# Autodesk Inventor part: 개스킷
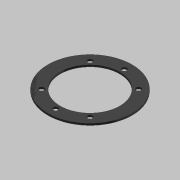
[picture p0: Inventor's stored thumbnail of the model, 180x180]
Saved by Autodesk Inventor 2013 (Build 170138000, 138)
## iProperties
Created: 2018-06
Part Number: 개스킷
Material: 고무
Document SubType Name: Modeling
Designer: G4400
Density: 0.93 g/cm^3
Mass: 2.2055 g
Surface Area: 37.9819 cm^2
Volume: 2.37151 cm^3
Author: G4400
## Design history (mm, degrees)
sketch "스케치1"
  geometry: C1 r 32.5 at (0, 0); C2 r 23 at (0, 0); 1 further point
  constraints: 2 centre point, 2 coincident
  dimensions: "d0" = 65 diameter of C1; "d1" = 46 diameter of C2
extrude "돌출1" new body sketch "스케치1" distance "d2" = 1.5; taper "d3" = 0 deg
sketch "스케치2" dims "d5" = 26.5
  geometry: C1 r 23 at (0, 0) reference; C2 r 32.5 at (0, 0) reference; 2 further points
  constraints: 2 vertical alignment, 1 coincident, 2 other
hole "구멍1" sketch "스케치2" at (0, 26.5) diameter "d11" = 4; stored, may be unused: countersink angle "d15" = 90 deg, drill point angle "d17" = 118 deg; dims "d12" = 6, "d13" = 4, "d14" = 2, "d16" = 8
node "솔리드1"
pattern_circular "원형 패턴1" dims angle "d19" = 360 deg
